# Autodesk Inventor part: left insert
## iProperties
Author: Rich
Shininess: 20.0
PropertySet Name: _Private Model Information
Created: 2001-04
Part Number: left insert
Document SubType Name: Sheet Metal
Designer: Rich
Control State: 0
Master: False
Checked Out: False
PropertySet Name: Design Tracking Control
Density: 0.0
Volumn: 0.0
Area: 0.0
PropertySet Name: Model Information
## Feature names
1. Extrusion1
2. Cut1
3. Corner Round1
4. Hole1
5. Plate1
6. Plate3
7. Bend2
